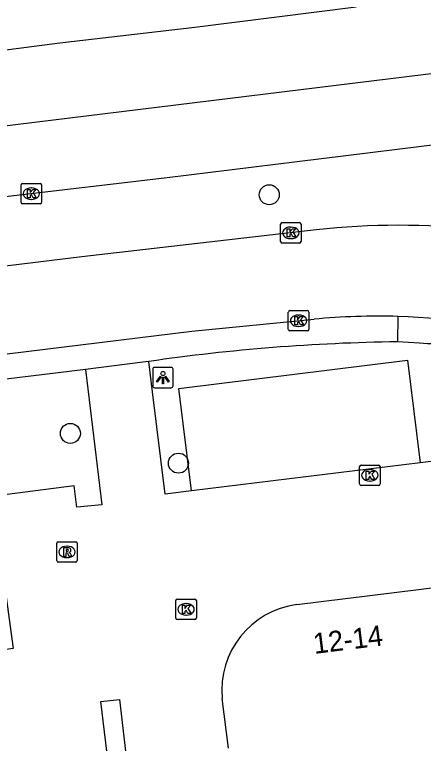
# Model space of a CAD drawing. Extents: x 161477 to 163040, y 383680 to 384868.
# Drawn here: x 161938.96 to 161958.93, y 383998.38 to 384033.98 of the extents above; entities that cross this region are included whole.
import ezdxf

# ---------------------------------------------------------------- set-up
doc = ezdxf.new("R2010")
doc.units = 0
for name, color, linetype in [('IMGEO_Boom', 7, 'Continuous'), ('IMGEO_Kolk', 7, 'Continuous'), ('IMGEO_Lichtpunt', 7, 'Continuous'), ('IMGEO_Pand', 7, 'Continuous'), ('IMGEO_Pand_nummerreeks', 7, 'Continuous'), ('IMGEO_Parkeervlak_open', 7, 'Continuous'), ('IMGEO_Rijbaan_lokaal_gesloten', 7, 'Continuous'), ('IMGEO_Rijbaan_lokaal_open', 7, 'Continuous'), ('IMGEO_Rioolput', 7, 'Continuous'), ('IMGEO_Voetpad_open', 7, 'Continuous')]:
    doc.layers.add(name, color=color, linetype=linetype)

msp = doc.modelspace()

# ---------------------------------------------------------------- linework, layer by layer
at = {"layer": 'IMGEO_Boom'}
for centre in [(161951.397, 384025.182), (161941.681, 384013.525), (161946.961, 384012.071)]:
    msp.add_circle(centre, 0.489, dxfattribs=at)
at = {"layer": 'IMGEO_Kolk'}
for p, q in [((161939.274, 384024.81), (161939.274, 384025.662)), ((161939.349, 384025.736), (161940.201, 384025.736)), ((161940.275, 384025.662), (161940.275, 384024.81)), ((161939.762, 384025.516), (161939.787, 384025.516)), ((161939.785, 384024.956), (161939.76, 384024.956)), ((161940.201, 384024.736), (161939.349, 384024.736)), ((161952.027, 384023.821), (161952.879, 384023.821)), ((161951.952, 384022.895), (161951.952, 384023.747)), ((161952.44, 384023.601), (161952.465, 384023.601)), ((161952.953, 384023.747), (161952.953, 384022.895)), ((161952.463, 384023.041), (161952.438, 384023.041)), ((161952.879, 384022.821), (161952.027, 384022.821)), ((161952.404, 384019.528), (161953.256, 384019.528)), ((161952.329, 384018.602), (161952.329, 384019.454)), ((161952.817, 384019.308), (161952.842, 384019.308)), ((161953.33, 384019.454), (161953.33, 384018.602)), ((161953.256, 384018.528), (161952.404, 384018.528)), ((161952.84, 384018.748), (161952.815, 384018.748)), ((161955.81, 384011.052), (161955.81, 384011.904)), ((161955.885, 384011.978), (161956.737, 384011.978)), ((161956.298, 384011.758), (161956.323, 384011.758)), ((161956.811, 384011.904), (161956.811, 384011.052)), ((161956.737, 384010.978), (161955.885, 384010.978)), ((161956.321, 384011.198), (161956.296, 384011.198)), ((161946.835, 384004.501), (161946.835, 384005.353)), ((161946.91, 384005.427), (161947.762, 384005.427)), ((161947.836, 384005.353), (161947.836, 384004.501)), ((161947.323, 384005.207), (161947.348, 384005.207)), ((161947.346, 384004.647), (161947.321, 384004.647)), ((161947.762, 384004.427), (161946.91, 384004.427))]:
    msp.add_line(p, q, dxfattribs=at)
for points in [[(161939.274, 384024.81), (161939.274, 384025.662)], [(161939.349, 384025.736), (161940.201, 384025.736)], [(161940.275, 384025.662), (161940.275, 384024.81)], [(161939.595, 384025.436), (161939.718, 384025.436), (161939.718, 384025.285), (161939.848, 384025.436), (161940.012, 384025.436), (161939.866, 384025.285), (161940.019, 384025.036), (161939.867, 384025.036), (161939.782, 384025.2), (161939.718, 384025.133), (161939.718, 384025.036), (161939.595, 384025.036), (161939.595, 384025.436)], [(161940.201, 384024.736), (161939.349, 384024.736)], [(161952.027, 384023.821), (161952.879, 384023.821)], [(161951.952, 384022.895), (161951.952, 384023.747)], [(161952.273, 384023.521), (161952.396, 384023.521), (161952.396, 384023.37), (161952.526, 384023.521), (161952.69, 384023.521), (161952.544, 384023.37), (161952.697, 384023.121), (161952.545, 384023.121), (161952.46, 384023.285), (161952.396, 384023.218), (161952.396, 384023.121), (161952.273, 384023.121), (161952.273, 384023.521)], [(161952.953, 384023.747), (161952.953, 384022.895)], [(161952.879, 384022.821), (161952.027, 384022.821)], [(161952.404, 384019.528), (161953.256, 384019.528)], [(161952.329, 384018.602), (161952.329, 384019.454)], [(161952.65, 384019.228), (161952.773, 384019.228), (161952.773, 384019.077), (161952.903, 384019.228), (161953.067, 384019.228), (161952.921, 384019.077), (161953.074, 384018.828), (161952.922, 384018.828), (161952.837, 384018.992), (161952.773, 384018.925), (161952.773, 384018.828), (161952.65, 384018.828), (161952.65, 384019.228)], [(161953.33, 384019.454), (161953.33, 384018.602)], [(161953.256, 384018.528), (161952.404, 384018.528)], [(161955.81, 384011.052), (161955.81, 384011.904)], [(161955.885, 384011.978), (161956.737, 384011.978)], [(161956.131, 384011.678), (161956.254, 384011.678), (161956.254, 384011.527), (161956.384, 384011.678), (161956.548, 384011.678), (161956.402, 384011.527), (161956.555, 384011.278), (161956.403, 384011.278), (161956.318, 384011.442), (161956.254, 384011.375), (161956.254, 384011.278), (161956.131, 384011.278), (161956.131, 384011.678)], [(161956.811, 384011.904), (161956.811, 384011.052)], [(161956.737, 384010.978), (161955.885, 384010.978)], [(161946.835, 384004.501), (161946.835, 384005.353)], [(161946.91, 384005.427), (161947.762, 384005.427)], [(161947.836, 384005.353), (161947.836, 384004.501)], [(161947.156, 384005.127), (161947.279, 384005.127), (161947.279, 384004.976), (161947.409, 384005.127), (161947.573, 384005.127), (161947.427, 384004.976), (161947.58, 384004.727), (161947.428, 384004.727), (161947.343, 384004.891), (161947.279, 384004.824), (161947.279, 384004.727), (161947.156, 384004.727), (161947.156, 384005.127)], [(161947.762, 384004.427), (161946.91, 384004.427)]]:
    msp.add_lwpolyline(points, dxfattribs=at)
for centre, start, end in [((161939.351, 384025.66), 91.552, 178.448), ((161939.351, 384025.66), 91.552, 178.448), ((161940.199, 384025.66), 1.552, 88.448), ((161940.199, 384025.66), 1.552, 88.448), ((161939.351, 384024.812), 181.552, 268.448), ((161939.351, 384024.812), 181.552, 268.448), ((161940.199, 384024.812), 271.552, 358.448), ((161940.199, 384024.812), 271.552, 358.448), ((161952.029, 384023.745), 91.552, 178.448), ((161952.029, 384023.745), 91.552, 178.448), ((161952.877, 384023.745), 1.552, 88.448), ((161952.877, 384023.745), 1.552, 88.448), ((161952.029, 384022.897), 181.552, 268.448), ((161952.029, 384022.897), 181.552, 268.448), ((161952.877, 384022.897), 271.552, 358.448), ((161952.877, 384022.897), 271.552, 358.448), ((161952.406, 384019.452), 91.552, 178.448), ((161952.406, 384019.452), 91.552, 178.448), ((161953.254, 384019.452), 1.552, 88.448), ((161953.254, 384019.452), 1.552, 88.448), ((161952.406, 384018.604), 181.552, 268.448), ((161952.406, 384018.604), 181.552, 268.448), ((161953.254, 384018.604), 271.552, 358.448), ((161953.254, 384018.604), 271.552, 358.448), ((161955.887, 384011.902), 91.552, 178.448), ((161955.887, 384011.902), 91.552, 178.448), ((161956.735, 384011.902), 1.552, 88.448), ((161956.735, 384011.902), 1.552, 88.448), ((161955.887, 384011.054), 181.552, 268.448), ((161955.887, 384011.054), 181.552, 268.448), ((161956.735, 384011.054), 271.552, 358.448), ((161956.735, 384011.054), 271.552, 358.448), ((161946.912, 384005.351), 91.552, 178.448), ((161946.912, 384005.351), 91.552, 178.448), ((161947.76, 384005.351), 1.552, 88.448), ((161947.76, 384005.351), 1.552, 88.448), ((161946.912, 384004.503), 181.552, 268.448), ((161946.912, 384004.503), 181.552, 268.448), ((161947.76, 384004.503), 271.552, 358.448), ((161947.76, 384004.503), 271.552, 358.448)]:
    msp.add_arc(centre, 0.0765, start, end, dxfattribs=at)
for centre, major_axis, ratio, start_param, end_param in [((161939.761, 384025.236), (-0.387, 0.002), 0.722429, 4.712389, 7.853982), ((161939.786, 384025.236), (-0.39, 0.002), 0.717154, 1.570796, 4.712389), ((161952.439, 384023.321), (-0.387, 0.002), 0.722429, 4.712389, 7.853982), ((161952.464, 384023.321), (-0.39, 0.002), 0.717154, 1.570796, 4.712389), ((161952.816, 384019.028), (-0.387, 0.002), 0.722429, 4.712389, 7.853982), ((161952.841, 384019.028), (-0.39, 0.002), 0.717154, 1.570796, 4.712389), ((161956.297, 384011.478), (-0.387, 0.002), 0.722429, 4.712389, 7.853982), ((161956.322, 384011.478), (-0.39, 0.002), 0.717154, 1.570796, 4.712389), ((161947.322, 384004.927), (-0.387, 0.002), 0.722429, 4.712389, 7.853982), ((161947.347, 384004.927), (-0.39, 0.002), 0.717154, 1.570796, 4.712389)]:
    msp.add_ellipse(centre, major_axis=major_axis, ratio=ratio, start_param=start_param, end_param=end_param, dxfattribs=at)
at = {"layer": 'IMGEO_Lichtpunt'}
for p, q in [((161945.703, 384016.654), (161945.703, 384015.847)), ((161945.703, 384016.654), (161945.703, 384015.847)), ((161946.605, 384016.749), (161945.797, 384016.749)), ((161946.605, 384016.749), (161945.797, 384016.749)), ((161946.699, 384015.847), (161946.699, 384016.654)), ((161946.699, 384015.847), (161946.699, 384016.654)), ((161945.797, 384015.753), (161946.605, 384015.753)), ((161945.797, 384015.753), (161946.605, 384015.753))]:
    msp.add_line(p, q, dxfattribs=at)
for points in [[(161946.077, 384016.318), (161946.116, 384016.29), (161945.928, 384016.028), (161945.89, 384016.055), (161946.077, 384016.318)], [(161946.289, 384016.29), (161946.327, 384016.317), (161946.514, 384016.055), (161946.475, 384016.027), (161946.289, 384016.29)], [(161946.179, 384016.27), (161946.226, 384016.27), (161946.226, 384015.948), (161946.179, 384015.948), (161946.179, 384016.27)]]:
    msp.add_lwpolyline(points, dxfattribs=at)
msp.add_circle((161946.202, 384016.452), 0.0994, dxfattribs=at)
for centre, start, end in [((161945.797, 384016.654), 90, 180), ((161945.797, 384016.654), 90, 180), ((161946.605, 384016.654), 0, 90), ((161946.605, 384016.654), 0, 90), ((161945.797, 384015.847), 180, 270), ((161945.797, 384015.847), 180, 270), ((161946.605, 384015.847), 270, 0), ((161946.605, 384015.847), 270, 360)]:
    msp.add_arc(centre, 0.0946, start, end, dxfattribs=at)
at = {"layer": 'IMGEO_Pand'}
for points in [[(161952.749, 384005.163), (161962.246, 384006.341), (161962.423, 384004.917), (161963.181, 383998.816)], [(161949.412, 383998.153), (161949.098, 384000.565)]]:
    msp.add_lwpolyline(points, dxfattribs=at)
msp.add_arc((161953.297, 384000.979), 4.219, 97.4614, 185.6366, dxfattribs=at)
at = {"layer": 'IMGEO_Parkeervlak_open'}
msp.add_lwpolyline([(161947.593, 384010.713), (161946.977, 384015.718), (161958.152, 384017.096), (161958.768, 384012.088)], dxfattribs=at)
at = {"layer": 'IMGEO_Rijbaan_lokaal_gesloten'}
for points in [[(161696.618, 383999.076), (161717.081, 384001.544), (161768.879, 384007.897), (161825.477, 384014.75), (161917.35, 384025.954), (162007.495, 384037.033), (162008.923, 384037.209), (162102.422, 384048.613), (162177.172, 384057.667), (162248.391, 384066.39)], [(162036.516, 384037.016), (162009.54, 384033.893), (162008.109, 384033.699), (162000, 384032.599), (161996.88, 384032.194), (161990.538, 384031.465), (161981.752, 384030.422), (161974.434, 384029.511), (161966.996, 384028.578), (161961.213, 384027.84), (161952.768, 384026.784), (161946.406, 384026.014), (161938.648, 384025.104), (161928.777, 384023.886), (161920.55, 384022.895), (161914.21, 384022.046), (161904.857, 384020.891), (161896.801, 384019.864), (161888.804, 384018.877), (161880.897, 384017.893), (161873.318, 384016.997), (161865.049, 384016.046), (161854.527, 384014.894)], [(161955.645, 384034.342), (161947.767, 384033.359), (161941.167, 384032.594), (161932.884, 384031.511), (161926.538, 384030.732), (161918.49, 384029.795), (161912.208, 384029.026), (161904.739, 384028.152), (161898.618, 384027.408), (161892.7, 384026.697), (161887.995, 384026.183), (161881.096, 384025.303), (161875.103, 384024.611), (161868.493, 384023.755), (161862.148, 384023.025), (161854.166, 384022.062), (161823.343, 384018.177), (161748.637, 384009.081), (161744.626, 384008.574)], [(161953.69, 384023.463), (161942.24, 384022.146), (161865.698, 384012.787), (161859.469, 384012.052), (161858.533, 384011.921)], [(161908.859, 384013.757), (161947.609, 384018.515), (161953.587, 384019.102)]]:
    msp.add_lwpolyline(points, dxfattribs=at)
for centre, radius, start, end in [((161957.72, 383988.002), 35.689, 70.7507, 96.4837), ((161956.706, 383986.424), 32.827, 88.2936, 95.453), ((161956.72, 383986.183), 33.067, 74.5816, 88.3289)]:
    msp.add_arc(centre, radius, start, end, dxfattribs=at)
at = {"layer": 'IMGEO_Rijbaan_lokaal_open'}
for points in [[(161960.334, 384017.808), (161960.403, 384017.097), (161960.843, 384012.611), (161960.869, 384012.347), (161960.628, 384012.317), (161958.768, 384012.088)], [(161945.514, 384017.038), (161945.225, 384016.996), (161942.419, 384016.653)], [(161947.593, 384010.713), (161946.312, 384010.555), (161945.696, 384015.56), (161945.514, 384017.038)], [(161942.419, 384016.653), (161943.227, 384010.041), (161941.996, 384009.912), (161941.867, 384010.958), (161930.899, 384009.549), (161930.999, 384008.59), (161937.988, 384009.484), (161938.22, 384007.825), (161938.827, 384003.48), (161938.893, 384003.011), (161938.193, 384002.912), (161937.564, 384002.823), (161937.489, 384002.813)], [(161958.768, 384012.088), (161947.593, 384010.713)], [(161943.521, 383997.465), (161943.172, 384000.421), (161944.089, 384000.523), (161944.432, 383997.577)]]:
    msp.add_lwpolyline(points, dxfattribs=at)
at = {"layer": 'IMGEO_Rioolput'}
for p, q in [((161941.016, 384007.307), (161941.016, 384008.159)), ((161941.091, 384008.233), (161941.943, 384008.233)), ((161942.017, 384008.159), (161942.017, 384007.307)), ((161941.504, 384008.013), (161941.529, 384008.013)), ((161941.527, 384007.453), (161941.502, 384007.453)), ((161941.943, 384007.233), (161941.091, 384007.233))]:
    msp.add_line(p, q, dxfattribs=at)
for points in [[(161941.016, 384007.307), (161941.016, 384008.159)], [(161941.091, 384008.233), (161941.943, 384008.233)], [(161942.017, 384008.159), (161942.017, 384007.307)], [(161941.605, 384007.931), (161941.353, 384007.933), (161941.353, 384007.533)], [(161941.531, 384007.852), (161941.477, 384007.852), (161941.477, 384007.771)], [(161941.477, 384007.771), (161941.529, 384007.771)], [(161941.353, 384007.533), (161941.477, 384007.533), (161941.477, 384007.695), (161941.488, 384007.695)], [(161941.535, 384007.666), (161941.606, 384007.533), (161941.746, 384007.533), (161941.681, 384007.659)], [(161941.943, 384007.233), (161941.091, 384007.233)]]:
    msp.add_lwpolyline(points, dxfattribs=at)
for centre, radius, start, end in [((161941.093, 384008.157), 0.0765, 91.552, 178.448), ((161941.093, 384008.157), 0.0765, 91.552, 178.448), ((161941.941, 384008.157), 0.0765, 1.552, 88.448), ((161941.941, 384008.157), 0.0765, 1.552, 88.448), ((161941.513, 384007.96), 0.19, 274.7715, 282.9687), ((161941.537, 384007.756), 0.0964, 77.0061, 93.1865), ((161941.551, 384007.813), 0.0378, 276.6634, 79.6772), ((161941.604, 384007.821), 0.109, 350.3612, 89.416), ((161941.602, 384007.821), 0.112, 277.5842, 350.9817), ((161941.487, 384007.642), 0.0533, 26.0293, 88.6989), ((161941.586, 384007.606), 0.108, 29.5134, 73.7905), ((161941.093, 384007.309), 0.0765, 181.552, 268.448), ((161941.093, 384007.309), 0.0765, 181.552, 268.448), ((161941.941, 384007.309), 0.0765, 271.552, 358.448), ((161941.941, 384007.309), 0.0765, 271.552, 358.448)]:
    msp.add_arc(centre, radius, start, end, dxfattribs=at)
for centre, major_axis, ratio, start_param, end_param in [((161941.503, 384007.733), (-0.387, 0.002), 0.722429, 4.712389, 7.853982), ((161941.528, 384007.733), (-0.39, 0.002), 0.717154, 1.570796, 4.712389)]:
    msp.add_ellipse(centre, major_axis=major_axis, ratio=ratio, start_param=start_param, end_param=end_param, dxfattribs=at)
at = {"layer": 'IMGEO_Voetpad_open'}
for points in [[(161957.684, 384019.236), (161957.662, 384017.999)], [(161958.733, 384017.931), (161957.662, 384017.999)], [(161942.419, 384016.653), (161909.941, 384012.689)]]:
    msp.add_lwpolyline(points, dxfattribs=at)
for centre, radius, start, end in [((161958.946, 383924.504), 93.504, 90.7869, 98.25933), ((161956.938, 383984.085), 33.893, 84.2494, 86.9641)]:
    msp.add_arc(centre, radius, start, end, dxfattribs=at)

# ---------------------------------------------------------------- texts
at = {"layer": 'IMGEO_Pand_nummerreeks'}
msp.add_text('12-14', height=1, rotation=7.0703, dxfattribs=at).set_placement((161953.603, 384002.75))

doc.saveas('drawing.dxf')
